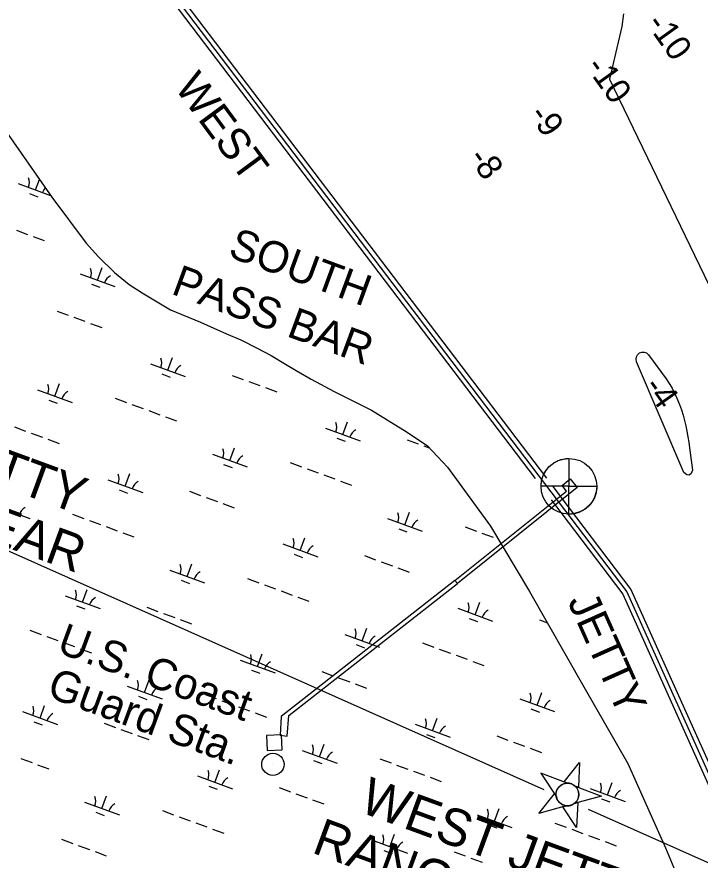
# Model space of a CAD drawing. Extents: x 3972907 to 3994831, y 172639 to 190852.
# Drawn here: x 3981252 to 3982172, y 185019 to 186154 of the extents above; entities that cross this region are included whole.
import ezdxf

# ---------------------------------------------------------------- set-up
doc = ezdxf.new("R2010")
doc.units = 0
for name, color, linetype in [('V-BLDG-IDEN', 7, 'Continuous'), ('V-BLDG-OTLN', 7, 'Continuous'), ('V-CHAN-DOCK', 7, 'Continuous'), ('V-CHAN-NAID', 7, 'Continuous'), ('V-RIVR-GAGE', 7, 'Continuous'), ('V-RIVR-IDEN', 7, 'Continuous'), ('V-RIVR-JETY', 7, 'Continuous'), ('V-RIVR-RANG', 7, 'Continuous'), ('V-TOPO-DPTH', 7, 'Continuous'), ('V-TOPO-MINR', 7, 'Continuous'), ('V-TOPO-TOWR', 7, 'Continuous'), ('V-WETL-SWMP', 7, 'Continuous')]:
    doc.layers.add(name, color=color, linetype=linetype)

msp = doc.modelspace()

# ---------------------------------------------------------------- linework, layer by layer
at = {"layer": 'V-BLDG-OTLN'}
msp.add_lwpolyline([(3981609.3, 185167.6), (3981608.4, 185187.6), (3981588.4, 185186.7), (3981589.3, 185166.7)], close=True, dxfattribs=at)
at = {"layer": 'V-CHAN-DOCK'}
for points in [[(3981842, 185395.5), (3981992.2, 185515.9), (3981986.1, 185523.4), (3981997.1, 185532.2), (3982006.3, 185520.8), (3981845.2, 185391.6), (3981842, 185395.5)], [(3981842, 185395.5), (3981608, 185212.4), (3981606.7, 185187.4), (3981615.9, 185186.1), (3981615.9, 185186.1), (3981618.5, 185213.7), (3981845.2, 185391.6)]]:
    msp.add_lwpolyline(points, dxfattribs=at)
at = {"layer": 'V-CHAN-NAID'}
for points in [[(3981993.2, 185122.6), (3981988.8, 185124.3), (3982009.6, 185150.5), (3982008.1, 185117.1), (3982003.6, 185118.7), (3982003, 185119.3), (3982002.1, 185119.9), (3982001.2, 185120.5), (3982000.3, 185121), (3981999.8, 185121.3), (3981999.1, 185121.6), (3981998.3, 185121.9), (3981997.6, 185122.1), (3981996.7, 185122.3), (3981996, 185122.4), (3981995.1, 185122.5), (3981994.3, 185122.6), (3981993.8, 185122.6)], [(3981993.2, 185122.6), (3981957.4, 185136.1), (3981978.5, 185104.2), (3981978.3, 185105.2), (3981978.2, 185106.1), (3981978.2, 185107.2), (3981978.2, 185108.3), (3981978.3, 185109), (3981978.4, 185109.8), (3981978.5, 185110.5), (3981978.7, 185111.3), (3981978.9, 185112.1), (3981979.2, 185112.9), (3981979.6, 185113.8), (3981980, 185114.6), (3981980.5, 185115.5), (3981981.1, 185116.4), (3981981.7, 185117.1), (3981982.3, 185117.8), (3981982.9, 185118.4), (3981983.6, 185119), (3981984.4, 185119.6), (3981985.1, 185120.2), (3981985.8, 185120.6), (3981986.5, 185120.9), (3981987.3, 185121.3), (3981988, 185121.6), (3981989, 185122), (3981989.7, 185122.2), (3981990.7, 185122.4), (3981991.7, 185122.5), (3981992.5, 185122.6)], [(3982003.6, 185118.7), (3982039.4, 185105.3), (3982002.6, 185095.1), (3982003.3, 185095.7), (3982004, 185096.4), (3982004.7, 185097), (3982005.3, 185097.8), (3982005.9, 185098.5), (3982006.4, 185099.2), (3982006.9, 185100.1), (3982007.2, 185100.8), (3982007.7, 185101.8), (3982008, 185102.8), (3982008.3, 185103.9), (3982008.5, 185104.8), (3982008.6, 185105.9), (3982008.7, 185107), (3982008.7, 185108.1), (3982008.6, 185108.8), (3982008.5, 185109.9), (3982008.3, 185110.9), (3982008, 185111.9), (3982007.7, 185112.9), (3982007.3, 185113.7), (3982006.8, 185114.7), (3982006.3, 185115.7), (3982005.7, 185116.5), (3982005, 185117.4), (3982004.4, 185118)], [(3981991.9, 185092.2), (3981955, 185082), (3981975.9, 185108.2), (3981978.5, 185104.2), (3981978.7, 185103.6), (3981979, 185102.5), (3981979.3, 185101.6), (3981979.7, 185100.6), (3981980.2, 185099.8), (3981980.7, 185099), (3981981.1, 185098.3), (3981981.8, 185097.5), (3981982.4, 185096.8), (3981983.1, 185096.1), (3981983.7, 185095.6), (3981984.4, 185095.1), (3981985.3, 185094.5), (3981986, 185094.1), (3981986.9, 185093.6), (3981987.6, 185093.3), (3981988.5, 185092.9), (3981989.3, 185092.7), (3981990.1, 185092.5), (3981991, 185092.3)], [(3982002.6, 185095.1), (3982007.2, 185096.4), (3982005.7, 185063), (3981987.3, 185090.9), (3981991.9, 185092.2), (3981992.8, 185092.1), (3981993.6, 185092.1), (3981994.8, 185092.2), (3981995.8, 185092.3), (3981996.8, 185092.5), (3981997.8, 185092.7), (3981998.8, 185093.1), (3981999.6, 185093.4), (3982000.5, 185093.8), (3982001.3, 185094.3), (3982002.1, 185094.8)]]:
    msp.add_lwpolyline(points, close=True, dxfattribs=at)
msp.add_circle((3981993.4, 185107.4), 15.3, dxfattribs=at)
at = {"layer": 'V-RIVR-GAGE'}
for points in [[(3981995.4, 185559.7), (3981995.4, 185522.2), (3981957.9, 185522.2), (3981957.9, 185523.2), (3981958, 185524.5), (3981958.1, 185526), (3981958.3, 185527.5), (3981958.5, 185528.9), (3981958.8, 185530.4), (3981959.1, 185531.7), (3981959.5, 185532.8), (3981959.8, 185534.1), (3981960.3, 185535.4), (3981960.8, 185536.6), (3981961.3, 185537.7), (3981961.9, 185539), (3981962.6, 185540.3), (3981963.3, 185541.5), (3981964, 185542.6), (3981965.2, 185544.4), (3981966, 185545.5), (3981967.1, 185546.8), (3981968.2, 185548), (3981969.1, 185548.9), (3981970.5, 185550.2), (3981971.7, 185551.2), (3981972.9, 185552.2), (3981974.5, 185553.3), (3981975.7, 185554.1), (3981977, 185554.8), (3981978.4, 185555.6), (3981979.8, 185556.3), (3981981.1, 185556.8), (3981982.9, 185557.5), (3981984.5, 185558.1), (3981986.1, 185558.5), (3981987.7, 185558.9), (3981989.4, 185559.2), (3981991.4, 185559.5), (3981992.9, 185559.6), (3981994.2, 185559.7)], [(3981995.4, 185484.7), (3981995.4, 185522.2), (3982032.9, 185522.2), (3982032.9, 185520.9), (3982032.8, 185519.3), (3982032.7, 185518), (3982032.5, 185516.7), (3982032.2, 185515.1), (3982031.9, 185513.6), (3982031.5, 185512), (3982031.2, 185510.9), (3982030.7, 185509.5), (3982030.1, 185508), (3982029.6, 185506.7), (3982029, 185505.5), (3982028.4, 185504.3), (3982027.7, 185503.1), (3982026.9, 185501.8), (3982026.1, 185500.6), (3982025.1, 185499.2), (3982024, 185497.9), (3982022.7, 185496.4), (3982021.5, 185495.3), (3982020.3, 185494.1), (3982019.2, 185493.2), (3982018.4, 185492.5), (3982017.1, 185491.6), (3982016.1, 185490.9), (3982014.8, 185490.1), (3982013.5, 185489.3), (3982012.2, 185488.6), (3982011.1, 185488.1), (3982010, 185487.6), (3982008.7, 185487.1), (3982007.3, 185486.6), (3982005.7, 185486.1), (3982004.1, 185485.7), (3982002.9, 185485.4), (3982001.5, 185485.2), (3982000.3, 185485), (3981998.9, 185484.8), (3981997.8, 185484.8), (3981996.5, 185484.7)]]:
    msp.add_lwpolyline(points, close=True, dxfattribs=at)
msp.add_circle((3981995.4, 185522.2), 37.5, dxfattribs=at)
at = {"layer": 'V-RIVR-JETY'}
for points in [[(3981252.2, 186461.5), (3981989.5, 185490.7), (3982073.3, 185380.3), (3982227.7, 185036.8)], [(3981361.2, 186307.7), (3981949.8, 185532.6)], [(3981371.6, 186314.6), (3981965, 185533.2)], [(3981973.6, 185521.9), (3981994.4, 185494.5), (3982078.8, 185383.5), (3982233.4, 185039.3)], [(3981971.5, 185504), (3981984.5, 185486.9), (3982067.9, 185377.1), (3982222, 185034.2)]]:
    msp.add_lwpolyline(points, dxfattribs=at)
msp.add_spline([(3980663.7, 188142.5), (3980923.3, 187897.8), (3981219.1, 187593.7), (3981381.5, 187411.2), (3981548.8, 187223.5), (3981746, 186997.4), (3981995.9, 186703.1), (3982288, 186350.3), (3982495.8, 186079.5), (3982762.8, 185654.7), (3982971, 185292.4), (3983111.2, 185037.5), (3983200, 184881.8), (3983229.9, 184826.4)], degree=3, dxfattribs=at)
at = {"layer": 'V-RIVR-RANG'}
for points in [[(3980961.3, 185559.7), (3981961.7, 185114.3)], [(3982021.3, 185087.7), (3990774.2, 181190.7)]]:
    msp.add_lwpolyline(points, dxfattribs=at)
at = {"layer": 'V-TOPO-DPTH'}
msp.add_lwpolyline([(3982068.9, 186158.2), (3982066.6, 186141.4), (3982049.8, 186070.1), (3982215.4, 185727.6)], dxfattribs=at)
at = {"layer": 'V-TOPO-MINR'}
for points in [[(3982068.9, 186158.2), (3982066.6, 186141.4), (3982049.8, 186070.1), (3982215.4, 185727.6)], [(3982157.4, 185537.1), (3982154, 185537.8), (3982150.1, 185540.6), (3982086.5, 185690), (3982085.9, 185693.5), (3982086.2, 185696.7), (3982087.8, 185699.4), (3982090.3, 185701.9), (3982093.6, 185702.9), (3982096.8, 185703), (3982099.6, 185701.7), (3982102.3, 185699.4), (3982126.1, 185667), (3982130.4, 185660.8), (3982134.3, 185654.4), (3982137.7, 185647.7), (3982140.8, 185640.8), (3982144.3, 185632.3), (3982146.9, 185625.3), (3982149.2, 185618.2), (3982151.1, 185611), (3982152.8, 185603.7), (3982154.2, 185596.3), (3982155.4, 185589), (3982156.6, 185581.5), (3982157.7, 185574.1), (3982161.8, 185543.8), (3982159.9, 185539.4), (3982157.4, 185537.1)]]:
    msp.add_lwpolyline(points, dxfattribs=at)
at = {"layer": 'V-TOPO-TOWR'}
msp.add_line((3981596.9, 185147.9), (3981596.9, 185147.9), dxfattribs=at)
msp.add_circle((3981596.9, 185147.9), 15, dxfattribs=at)
at = {"layer": 'V-WETL-SWMP'}
for p, q in [((3981253.9, 185930), (3981297.6, 185913.9)), ((3981277.4, 185921.3), (3981282.6, 185935.4)), ((3981269.1, 185916.2), (3981280.3, 185912)), ((3981251.6, 185866.9), (3981266.6, 185861.3)), ((3981274.1, 185858.6), (3981289.1, 185853.1)), ((3981360.8, 185799.7), (3981367, 185816.6)), ((3981337.3, 185808.3), (3981384.2, 185791.1)), ((3981352.5, 185794.5), (3981363.7, 185790.4)), ((3981306.4, 185758.2), (3981321.4, 185752.7)), ((3981328.9, 185749.9), (3981343.9, 185744.4)), ((3981351.5, 185741.6), (3981366.5, 185736.1)), ((3981455.5, 185678.6), (3981461.7, 185695.5)), ((3981432.1, 185687.3), (3981479, 185670)), ((3981447.2, 185673.5), (3981458.5, 185669.3)), ((3981541.9, 185671.6), (3981557, 185666.1)), ((3981303.4, 185643.6), (3981309.6, 185660.5)), ((3981564.5, 185663.3), (3981579.5, 185657.8)), ((3981279.9, 185652.2), (3981326.8, 185634.9)), ((3981587, 185655.1), (3981602, 185649.5)), ((3981295.1, 185638.4), (3981306.3, 185634.3)), ((3981384.7, 185640.7), (3981399.7, 185635.2)), ((3981407.2, 185632.4), (3981422.2, 185626.9)), ((3981429.7, 185624.2), (3981444.8, 185618.6)), ((3981452.3, 185615.9), (3981467.3, 185610.4)), ((3981249, 185602.1), (3981264, 185596.5)), ((3981667.6, 185600.7), (3981714.5, 185583.4)), ((3981691.1, 185592.1), (3981697.3, 185609)), ((3981271.5, 185593.8), (3981286.6, 185588.3)), ((3981294.1, 185585.5), (3981309.1, 185580)), ((3981682.8, 185586.9), (3981694.1, 185582.8)), ((3981777.5, 185585), (3981792.5, 185579.5)), ((3981538.9, 185557), (3981545.1, 185573.9)), ((3981800, 185576.8), (3981807.1, 185574.1)), ((3981515.5, 185565.6), (3981562.4, 185548.4)), ((3981530.6, 185551.8), (3981541.9, 185547.7)), ((3981620.2, 185554.1), (3981635.2, 185548.6)), ((3981642.8, 185545.9), (3981657.8, 185540.3)), ((3981398.1, 185522.5), (3981404.4, 185539.4)), ((3981665.3, 185537.6), (3981680.3, 185532.1)), ((3981374.7, 185531.1), (3981421.6, 185513.9)), ((3981687.8, 185529.3), (3981702.8, 185523.8)), ((3981389.9, 185517.3), (3981401.1, 185513.2)), ((3981484.6, 185515.5), (3981499.6, 185510)), ((3981507.1, 185507.2), (3981522.1, 185501.7)), ((3981529.6, 185498.9), (3981544.6, 185493.4)), ((3981222.5, 185496.1), (3981269.5, 185478.8)), ((3981774.5, 185470.4), (3981780.7, 185487.3)), ((3981327.3, 185484.6), (3981342.3, 185479.1)), ((3981349.8, 185476.3), (3981364.8, 185470.8)), ((3981751, 185479), (3981797.9, 185461.8)), ((3981372.3, 185468), (3981387.4, 185462.5)), ((3981766.2, 185465.2), (3981777.4, 185461.1)), ((3981855.8, 185467.6), (3981870.8, 185462)), ((3981394.9, 185459.8), (3981409.9, 185454.2)), ((3981633.7, 185435.9), (3981639.9, 185452.8)), ((3981878.3, 185459.3), (3981893.3, 185453.8)), ((3981610.2, 185444.6), (3981657.2, 185427.3)), ((3981625.4, 185430.8), (3981636.7, 185426.6)), ((3981720.1, 185428.9), (3981735.1, 185423.4)), ((3981742.6, 185420.6), (3981757.7, 185415.1)), ((3981458.1, 185409.5), (3981505, 185392.2)), ((3981481.5, 185400.9), (3981487.7, 185417.8)), ((3981765.2, 185412.4), (3981780.2, 185406.8)), ((3981562.8, 185398), (3981577.9, 185392.5)), ((3981473.2, 185395.7), (3981484.5, 185391.6)), ((3981585.4, 185389.7), (3981600.4, 185384.2)), ((3981317.3, 185375), (3981364.2, 185357.8)), ((3981340.8, 185366.4), (3981347, 185383.3)), ((3981607.9, 185381.5), (3981622.9, 185375.9)), ((3981630.4, 185373.2), (3981645.4, 185367.7)), ((3981869.2, 185349.4), (3981875.5, 185366.3)), ((3981332.5, 185361.2), (3981343.7, 185357.1)), ((3981427.2, 185359.4), (3981442.2, 185353.8)), ((3981449.7, 185351.1), (3981464.7, 185345.6)), ((3981845.8, 185358), (3981892.7, 185340.7)), ((3981472.2, 185342.8), (3981487.2, 185337.3)), ((3981861, 185344.2), (3981872.2, 185340.1)), ((3981955.7, 185342.3), (3981966.5, 185338.3)), ((3981269.9, 185328.5), (3981284.9, 185322.9)), ((3981717.1, 185314.3), (3981723.3, 185331.2)), ((3981292.4, 185320.2), (3981307.5, 185314.7)), ((3981693.6, 185322.9), (3981740.6, 185305.7)), ((3981315, 185311.9), (3981330, 185306.4)), ((3981708.8, 185309.1), (3981720.1, 185305)), ((3981798.4, 185311.4), (3981813.4, 185305.9)), ((3981337.5, 185303.6), (3981352.5, 185298.1)), ((3981576.3, 185279.8), (3981582.5, 185296.7)), ((3981820.9, 185303.2), (3981835.9, 185297.6)), ((3981843.4, 185294.9), (3981858.5, 185289.4)), ((3981552.8, 185288.4), (3981599.8, 185271.2)), ((3981866, 185286.6), (3981881, 185281.1)), ((3981568, 185274.6), (3981579.3, 185270.5)), ((3981662.7, 185272.8), (3981677.7, 185267.3)), ((3981424.2, 185244.7), (3981430.4, 185261.6)), ((3981685.3, 185264.5), (3981700.3, 185259)), ((3981400.7, 185253.4), (3981447.6, 185236.1)), ((3981707.8, 185256.2), (3981722.8, 185250.7)), ((3981415.9, 185239.6), (3981427.1, 185235.4)), ((3981505.5, 185241.9), (3981520.5, 185236.4)), ((3981952.6, 185227.7), (3981958.8, 185244.6)), ((3981283.4, 185210.3), (3981289.6, 185227.2)), ((3981528, 185233.6), (3981543, 185228.1)), ((3981929.2, 185236.3), (3981976.1, 185219.1)), ((3981259.9, 185218.9), (3981306.8, 185201.6)), ((3981550.5, 185225.3), (3981565.5, 185219.8)), ((3981573, 185217.1), (3981588.1, 185211.5)), ((3981944.3, 185222.5), (3981955.6, 185218.4)), ((3981275.1, 185205.1), (3981286.4, 185201)), ((3981369.8, 185203.2), (3981384.8, 185197.7)), ((3981811.9, 185193.2), (3981818.1, 185210.1)), ((3981392.3, 185195), (3981407.3, 185189.4)), ((3981788.4, 185201.9), (3981835.3, 185184.6)), ((3981414.8, 185186.7), (3981429.9, 185181.2)), ((3981803.6, 185188.1), (3981814.8, 185183.9)), ((3981898.3, 185186.2), (3981913.3, 185180.7)), ((3981659.7, 185158.2), (3981665.9, 185175.1)), ((3981920.8, 185177.9), (3981935.8, 185172.4)), ((3981943.3, 185169.7), (3981958.3, 185164.1)), ((3981636.2, 185166.8), (3981683.2, 185149.5)), ((3981257.6, 185155.8), (3981272.6, 185150.3)), ((3981280.1, 185147.5), (3981295.1, 185142)), ((3981651.4, 185153), (3981662.7, 185148.9)), ((3981741, 185155.3), (3981756, 185149.8)), ((3981763.5, 185147), (3981778.6, 185141.5)), ((3981518.9, 185123.7), (3981525.1, 185140.6)), ((3981786.1, 185138.8), (3981801.1, 185133.2)), ((3981495.5, 185132.3), (3981542.4, 185115.1)), ((3981808.6, 185130.5), (3981823.6, 185125)), ((3982047.4, 185106.7), (3982053.6, 185123.6)), ((3981510.6, 185118.5), (3981521.9, 185114.4)), ((3981605.3, 185116.7), (3981620.4, 185111.1)), ((3982023.9, 185115.3), (3982070.9, 185098)), ((3981366.8, 185088.6), (3981373, 185105.5)), ((3981627.9, 185108.4), (3981642.9, 185102.9)), ((3982039.1, 185101.5), (3982050.4, 185097.3)), ((3981343.3, 185097.2), (3981390.2, 185080)), ((3981650.4, 185100.1), (3981665.4, 185094.6)), ((3981358.5, 185083.4), (3981369.7, 185079.3)), ((3981448.1, 185085.8), (3981463.1, 185080.2)), ((3981871.8, 185080.2), (3981918.7, 185063)), ((3981895.3, 185071.6), (3981901.5, 185088.5)), ((3981470.6, 185077.5), (3981485.6, 185072)), ((3981493.1, 185069.2), (3981508.1, 185063.7)), ((3981976.6, 185068.7), (3981991.6, 185063.2)), ((3981515.7, 185060.9), (3981530.7, 185055.4)), ((3981887, 185066.4), (3981898.2, 185062.3)), ((3981999.1, 185060.5), (3982014.1, 185054.9)), ((3981312.4, 185047.1), (3981327.4, 185041.6)), ((3981731, 185045.7), (3981777.9, 185028.5)), ((3981754.5, 185037.1), (3981760.7, 185054)), ((3982021.6, 185052.2), (3982036.6, 185046.7)), ((3981334.9, 185038.8), (3981350, 185033.3)), ((3982044.1, 185043.9), (3982059.2, 185038.4)), ((3981357.5, 185030.5), (3981372.5, 185025)), ((3981746.2, 185031.9), (3981757.4, 185027.8)), ((3981840.9, 185030.1), (3981855.9, 185024.6)), ((3981863.4, 185021.8), (3981878.4, 185016.3))]:
    msp.add_line(p, q, dxfattribs=at)
for points in [[(3981237.4, 186000.1), (3981299.3, 185911.5), (3981345.3, 185849.7), (3981362, 185831), (3981383.6, 185810), (3981403.4, 185794.1), (3981420.9, 185782.7), (3981458.9, 185760), (3981499.4, 185743.3), (3981517.2, 185735), (3981534.6, 185727.4), (3981553.6, 185719.2), (3981575.7, 185708.3), (3981594.5, 185698.2), (3981614, 185686.7), (3981628.2, 185678.1), (3981648.4, 185666.6), (3981679.5, 185649.9), (3981729.6, 185624.7), (3981777.7, 185595), (3981804.8, 185576.6), (3981831.9, 185548.2), (3981889.8, 185468.5), (3981942.4, 185380.8)], [(3981942.4, 185380.8), (3982015.3, 185252.4), (3982074.7, 185149), (3982125.6, 185035.4), (3982161.2, 184949.4), (3982180.3, 184890.4), (3982185, 184841.7), (3982182.9, 184752.3), (3982177.8, 184609.4), (3982171.5, 184470.8), (3982161.8, 184311.9), (3982156.7, 184185.6), (3982155.9, 184088.1), (3982163.1, 184030)]]:
    msp.add_lwpolyline(points, dxfattribs=at)
for centre, start, end in [((3981251.5, 185931.1), 339.0473, 20.5909), ((3981303.4, 185912), 136.9519, 160.5909), ((3981334.9, 185809.4), 339.0473, 20.5909), ((3981386.8, 185790.4), 119.0473, 160.5909), ((3981429.7, 185688.4), 339.0473, 20.5909), ((3981481.5, 185669.3), 119.0473, 160.5909), ((3981277.5, 185653.3), 339.0473, 20.5909), ((3981329.4, 185634.3), 119.0473, 160.5909), ((3981665.2, 185601.8), 339.0473, 20.5909), ((3981717.1, 185582.8), 119.0473, 160.5909), ((3981513.1, 185566.7), 339.0473, 20.5909), ((3981564.9, 185547.7), 119.0473, 160.5909), ((3981372.3, 185532.3), 339.0473, 20.5909), ((3981424.2, 185513.2), 119.0473, 160.5909), ((3981272, 185478.1), 119.0473, 160.5909), ((3981748.6, 185480.2), 339.0473, 20.5909), ((3981800.5, 185461.1), 119.0473, 160.5909), ((3981607.9, 185445.7), 339.0473, 20.5909), ((3981659.7, 185426.6), 119.0473, 160.5909), ((3981455.7, 185410.6), 339.0473, 20.5909), ((3981507.5, 185391.6), 119.0473, 160.5909), ((3981314.9, 185376.1), 339.0473, 20.5909), ((3981366.8, 185357.1), 119.0473, 160.5909), ((3981843.4, 185359.1), 339.0473, 20.5909), ((3981895.3, 185340.1), 119.0473, 160.5909), ((3981691.2, 185324), 339.0473, 20.5909), ((3981743.1, 185305), 119.0473, 160.5909), ((3981550.5, 185289.6), 339.0473, 20.5909), ((3981602.3, 185270.5), 119.0473, 160.5909), ((3981398.3, 185254.5), 339.0473, 20.5909), ((3981450.2, 185235.4), 119.0473, 160.5909), ((3981926.8, 185237.5), 339.0473, 20.5909), ((3981257.5, 185220), 339.0473, 20.5909), ((3981978.6, 185218.4), 119.0473, 160.5909), ((3981309.4, 185201), 119.0473, 160.5909), ((3981786, 185203), 339.0473, 20.5909), ((3981837.9, 185183.9), 119.0473, 160.5909), ((3981633.9, 185167.9), 339.0473, 20.5909), ((3981685.7, 185148.9), 119.0473, 160.5909), ((3981493.1, 185133.4), 339.0473, 20.5909), ((3981544.9, 185114.4), 119.0473, 160.5909), ((3982021.6, 185116.4), 339.0473, 20.5909), ((3982073.4, 185097.4), 119.0473, 160.5909), ((3981340.9, 185098.4), 339.0473, 20.5909), ((3981392.8, 185079.3), 119.0473, 160.5909), ((3981869.4, 185081.3), 339.0473, 20.5909), ((3981921.3, 185062.3), 119.0473, 160.5909), ((3981728.6, 185046.9), 339.0473, 20.5909), ((3981780.5, 185027.8), 119.0473, 160.5909)]:
    msp.add_arc(centre, 17.6, start, end, dxfattribs=at)

# ---------------------------------------------------------------- texts
at = {"layer": 'V-BLDG-IDEN'}
for s, p in [('U.S. Coast', (3981304.1, 185299.4)), ('Guard Sta.', (3981290.8, 185239.7))]:
    msp.add_text(s, height=42, rotation=339.819, dxfattribs=at).set_placement(p)
at = {"layer": 'V-CHAN-NAID'}
for s, p in [('WEST JETTY', (3980943.8, 185627.5)), ('RANGE REAR', (3980918, 185557.4)), ('WEST JETTY', (3981711.2, 185084.7)), ('RANGE FRONT', (3981647.6, 185029.6))]:
    msp.add_text(s, height=50, rotation=339.8623, dxfattribs=at).set_placement(p)
at = {"layer": 'V-RIVR-IDEN'}
for s, rotation, p in [('WEST', 306.4164, (3981463.4, 186059.4)), ('SOUTH', 339.819, (3981534.9, 185831.9)), ('PASS BAR', 339.819, (3981458.5, 185781.8)), ('JETTY', 294.1025, (3981993.1, 185367.6))]:
    msp.add_text(s, height=42, rotation=rotation, dxfattribs=at).set_placement(p)
at = {"layer": 'V-RIVR-RANG'}
for s, rotation, p in [('-10', 305.5709, (3982098.4, 186145.1)), ('-10', 305.5709, (3982017.1, 186087)), ('-9', 305.5709, (3981940.5, 186022.1)), ('-8', 305.5709, (3981859, 185964.3)), ('-4', 305.1039, (3982094.9, 185656.5))]:
    msp.add_text(s, height=33.5, rotation=rotation, dxfattribs=at).set_placement(p)

doc.saveas('drawing.dxf')
